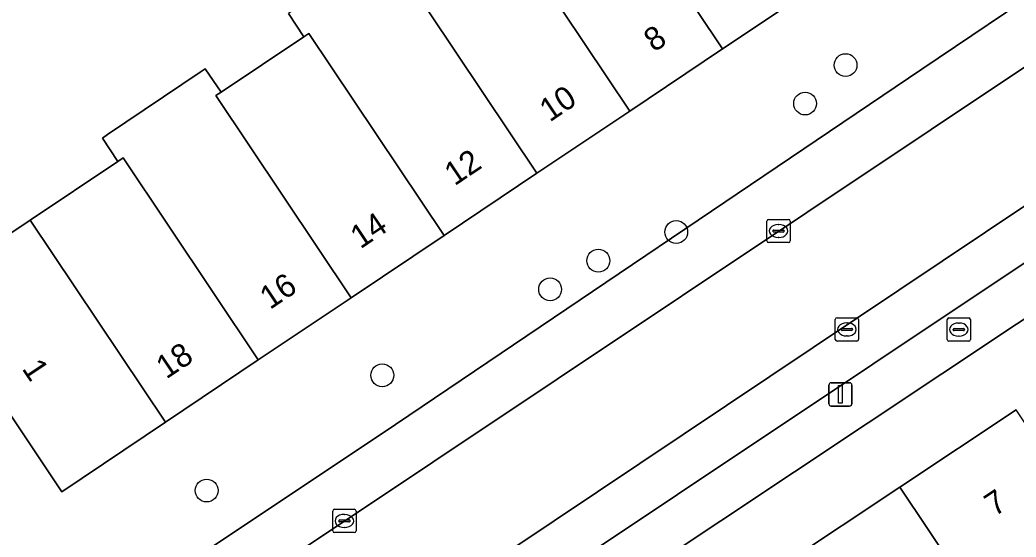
# Model space of a CAD drawing. Extents: x 158352 to 159489, y 383828 to 384603.
# Drawn here: x 158810.26 to 158853.05, y 384458.72 to 384480.93 of the extents above; entities that cross this region are included whole.
import ezdxf

# ---------------------------------------------------------------- set-up
doc = ezdxf.new("R2010")
doc.units = 0
for name, color, linetype in [('IMGEO_Boom', 7, 'Continuous'), ('IMGEO_Brandkraan', 7, 'Continuous'), ('IMGEO_Erf', 7, 'Continuous'), ('IMGEO_Groenvoorziening', 7, 'Continuous'), ('IMGEO_Kolk', 7, 'Continuous'), ('IMGEO_Lichtmast', 7, 'Continuous'), ('IMGEO_Pand', 7, 'Continuous'), ('IMGEO_Pand_nummerreeks', 7, 'Continuous'), ('IMGEO_Parkeervlak_open', 7, 'Continuous'), ('IMGEO_Rijbaan_lokaal_open', 7, 'Continuous'), ('IMGEO_Voetpad_open', 7, 'Continuous')]:
    doc.layers.add(name, color=color, linetype=linetype)

msp = doc.modelspace()

# ---------------------------------------------------------------- linework, layer by layer
at = {"layer": 'IMGEO_Boom'}
for centre in [(158845.724, 384478.986), (158843.983, 384477.337), (158838.451, 384471.819), (158835.105, 384470.589), (158833.035, 384469.358), (158825.826, 384465.668), (158818.282, 384460.72)]:
    msp.add_circle(centre, 0.489, dxfattribs=at)
at = {"layer": 'IMGEO_Brandkraan'}
for p, q in [((158850.087, 384467.205), (158850.087, 384468.057)), ((158850.162, 384468.131), (158851.014, 384468.131)), ((158850.575, 384467.911), (158850.6, 384467.911)), ((158851.088, 384468.057), (158851.088, 384467.205)), ((158850.346, 384467.625), (158850.346, 384467.637)), ((158850.784, 384467.588), (158850.386, 384467.588)), ((158850.389, 384467.674), (158850.787, 384467.674)), ((158850.83, 384467.637), (158850.83, 384467.625)), ((158851.014, 384467.131), (158850.162, 384467.131)), ((158850.598, 384467.351), (158850.573, 384467.351))]:
    msp.add_line(p, q, dxfattribs=at)
for points in [[(158850.087, 384467.205), (158850.087, 384468.057)], [(158850.162, 384468.131), (158851.014, 384468.131)], [(158851.088, 384468.057), (158851.088, 384467.205)], [(158851.014, 384467.131), (158850.162, 384467.131)]]:
    msp.add_lwpolyline(points, dxfattribs=at)
for centre, radius, start, end in [((158850.164, 384468.055), 0.0765, 91.552, 178.448), ((158850.164, 384468.055), 0.0765, 91.552, 178.448), ((158851.012, 384468.055), 0.0765, 1.552, 88.448), ((158851.012, 384468.055), 0.0765, 1.552, 88.448), ((158850.386, 384467.634), 0.0403, 85.8775, 175.7526), ((158850.383, 384467.624), 0.0366, 178.938, 274.7102), ((158850.787, 384467.631), 0.043, 264.8664, 352.4533), ((158850.791, 384467.636), 0.0386, 1.7309, 96.639), ((158850.164, 384467.207), 0.0765, 181.552, 268.448), ((158850.164, 384467.207), 0.0765, 181.552, 268.448), ((158851.012, 384467.207), 0.0765, 271.552, 358.448), ((158851.012, 384467.207), 0.0765, 271.552, 358.448)]:
    msp.add_arc(centre, radius, start, end, dxfattribs=at)
for centre, major_axis, ratio, start_param, end_param in [((158850.574, 384467.631), (-0.387, 0.002), 0.722429, 4.712389, 7.853982), ((158850.599, 384467.631), (-0.39, 0.002), 0.717154, 1.570796, 4.712389)]:
    msp.add_ellipse(centre, major_axis=major_axis, ratio=ratio, start_param=start_param, end_param=end_param, dxfattribs=at)
at = {"layer": 'IMGEO_Erf'}
msp.add_lwpolyline([(158865.767, 384476.314), (158824.454, 384448.838), (158828.581, 384442.633), (158830.834, 384444.121), (158828.404, 384447.801), (158833.585, 384451.247), (158838.609, 384454.589), (158843.054, 384457.545), (158848.053, 384460.87), (158853.047, 384464.192)], dxfattribs=at)
at = {"layer": 'IMGEO_Groenvoorziening'}
for points in [[(158756.032, 384416.448), (158759.672, 384418.896), (158801.455, 384446.936), (158826.388, 384463.558), (158848.997, 384478.808), (158860.431, 384486.52)], [(158844.203, 384482.207), (158840.44, 384479.686), (158836.453, 384477.014), (158832.465, 384474.342), (158828.477, 384471.67), (158824.49, 384468.999), (158820.502, 384466.326), (158816.515, 384463.655), (158812.057, 384460.668), (158806.248, 384469.347), (158810.709, 384472.333), (158814.475, 384474.854), (158813.806, 384475.854), (158814.028, 384476.004), (158818.009, 384478.687), (158818.219, 384478.828), (158818.901, 384477.824), (158822.457, 384480.205), (158821.791, 384481.2)]]:
    msp.add_lwpolyline(points, dxfattribs=at)
at = {"layer": 'IMGEO_Kolk'}
for p, q in [((158842.344, 384471.437), (158842.344, 384472.289)), ((158842.419, 384472.363), (158843.271, 384472.363)), ((158842.832, 384472.143), (158842.857, 384472.143)), ((158843.345, 384472.289), (158843.345, 384471.437)), ((158842.603, 384471.857), (158842.603, 384471.869)), ((158843.041, 384471.82), (158842.643, 384471.82)), ((158842.646, 384471.906), (158843.044, 384471.906)), ((158843.087, 384471.869), (158843.087, 384471.857)), ((158843.271, 384471.363), (158842.419, 384471.363)), ((158842.855, 384471.583), (158842.83, 384471.583)), ((158845.28, 384467.212), (158845.28, 384468.064)), ((158845.355, 384468.138), (158846.207, 384468.138)), ((158845.768, 384467.918), (158845.793, 384467.918)), ((158846.281, 384468.064), (158846.281, 384467.212)), ((158845.539, 384467.632), (158845.539, 384467.644)), ((158845.977, 384467.595), (158845.579, 384467.595)), ((158845.582, 384467.681), (158845.98, 384467.681)), ((158845.791, 384467.358), (158845.766, 384467.358)), ((158846.023, 384467.644), (158846.023, 384467.632)), ((158846.207, 384467.138), (158845.355, 384467.138)), ((158823.697, 384458.988), (158823.697, 384459.84)), ((158823.772, 384459.914), (158824.624, 384459.914)), ((158824.185, 384459.694), (158824.21, 384459.694)), ((158824.698, 384459.84), (158824.698, 384458.988)), ((158823.956, 384459.408), (158823.956, 384459.42)), ((158824.394, 384459.371), (158823.996, 384459.371)), ((158823.999, 384459.457), (158824.397, 384459.457)), ((158824.44, 384459.42), (158824.44, 384459.408)), ((158824.624, 384458.914), (158823.772, 384458.914)), ((158824.208, 384459.134), (158824.183, 384459.134))]:
    msp.add_line(p, q, dxfattribs=at)
for points in [[(158842.344, 384471.437), (158842.344, 384472.289)], [(158842.419, 384472.363), (158843.271, 384472.363)], [(158843.345, 384472.289), (158843.345, 384471.437)], [(158843.271, 384471.363), (158842.419, 384471.363)], [(158845.28, 384467.212), (158845.28, 384468.064)], [(158845.355, 384468.138), (158846.207, 384468.138)], [(158846.281, 384468.064), (158846.281, 384467.212)], [(158846.207, 384467.138), (158845.355, 384467.138)], [(158823.697, 384458.988), (158823.697, 384459.84)], [(158823.772, 384459.914), (158824.624, 384459.914)], [(158824.698, 384459.84), (158824.698, 384458.988)], [(158824.624, 384458.914), (158823.772, 384458.914)]]:
    msp.add_lwpolyline(points, dxfattribs=at)
for centre, radius, start, end in [((158842.421, 384472.287), 0.0765, 91.552, 178.448), ((158842.421, 384472.287), 0.0765, 91.552, 178.448), ((158843.269, 384472.287), 0.0765, 1.552, 88.448), ((158843.269, 384472.287), 0.0765, 1.552, 88.448), ((158842.643, 384471.866), 0.0403, 85.8775, 175.7526), ((158842.64, 384471.856), 0.0366, 178.938, 274.7102), ((158843.044, 384471.863), 0.043, 264.8664, 352.4533), ((158843.048, 384471.868), 0.0386, 1.7309, 96.639), ((158842.421, 384471.439), 0.0765, 181.552, 268.448), ((158842.421, 384471.439), 0.0765, 181.552, 268.448), ((158843.269, 384471.439), 0.0765, 271.552, 358.448), ((158843.269, 384471.439), 0.0765, 271.552, 358.448), ((158845.357, 384468.062), 0.0765, 91.552, 178.448), ((158845.357, 384468.062), 0.0765, 91.552, 178.448), ((158846.205, 384468.062), 0.0765, 1.552, 88.448), ((158846.205, 384468.062), 0.0765, 1.552, 88.448), ((158845.579, 384467.641), 0.0403, 85.8775, 175.7526), ((158845.576, 384467.631), 0.0366, 178.938, 274.7102), ((158845.98, 384467.638), 0.043, 264.8664, 352.4533), ((158845.984, 384467.643), 0.0386, 1.7309, 96.639), ((158845.357, 384467.214), 0.0765, 181.552, 268.448), ((158845.357, 384467.214), 0.0765, 181.552, 268.448), ((158846.205, 384467.214), 0.0765, 271.552, 358.448), ((158846.205, 384467.214), 0.0765, 271.552, 358.448), ((158823.774, 384459.838), 0.0765, 91.552, 178.448), ((158823.774, 384459.838), 0.0765, 91.552, 178.448), ((158824.622, 384459.838), 0.0765, 1.552, 88.448), ((158824.622, 384459.838), 0.0765, 1.552, 88.448), ((158823.996, 384459.417), 0.0403, 85.8775, 175.7526), ((158823.993, 384459.407), 0.0366, 178.938, 274.7102), ((158824.397, 384459.414), 0.043, 264.8664, 352.4533), ((158824.401, 384459.419), 0.0386, 1.7309, 96.639), ((158823.774, 384458.99), 0.0765, 181.552, 268.448), ((158823.774, 384458.99), 0.0765, 181.552, 268.448), ((158824.622, 384458.99), 0.0765, 271.552, 358.448), ((158824.622, 384458.99), 0.0765, 271.552, 358.448)]:
    msp.add_arc(centre, radius, start, end, dxfattribs=at)
for centre, major_axis, ratio, start_param, end_param in [((158842.831, 384471.863), (-0.387, 0.002), 0.722429, 4.712389, 7.853982), ((158842.856, 384471.863), (-0.39, 0.002), 0.717154, 1.570796, 4.712389), ((158845.767, 384467.638), (-0.387, 0.002), 0.722429, 4.712389, 7.853982), ((158845.792, 384467.638), (-0.39, 0.002), 0.717154, 1.570796, 4.712389), ((158824.184, 384459.414), (-0.387, 0.002), 0.722429, 4.712389, 7.853982), ((158824.209, 384459.414), (-0.39, 0.002), 0.717154, 1.570796, 4.712389)]:
    msp.add_ellipse(centre, major_axis=major_axis, ratio=ratio, start_param=start_param, end_param=end_param, dxfattribs=at)
at = {"layer": 'IMGEO_Lichtmast'}
for p, q in [((158845.004, 384464.448), (158845.004, 384465.248)), ((158845.004, 384465.248), (158845.004, 384464.448)), ((158845.104, 384465.348), (158845.894, 384465.348)), ((158845.894, 384465.348), (158845.104, 384465.348)), ((158845.994, 384465.248), (158845.994, 384464.448)), ((158845.994, 384464.448), (158845.994, 384465.248)), ((158845.894, 384464.348), (158845.104, 384464.348)), ((158845.104, 384464.348), (158845.894, 384464.348))]:
    msp.add_line(p, q, dxfattribs=at)
msp.add_lwpolyline([(158845.424, 384465.223), (158845.574, 384465.223), (158845.574, 384464.473), (158845.424, 384464.473), (158845.424, 384465.223)], dxfattribs=at)
for centre, start, end in [((158845.104, 384465.248), 90, 180), ((158845.104, 384465.248), 90, 180), ((158845.894, 384465.248), 0, 90), ((158845.894, 384465.248), 360, 90), ((158845.104, 384464.448), 180, 270), ((158845.104, 384464.448), 180, 270), ((158845.894, 384464.448), 270, 0), ((158845.894, 384464.448), 270, 0)]:
    msp.add_arc(centre, 0.1, start, end, dxfattribs=at)
at = {"layer": 'IMGEO_Pand'}
for points in [[(158839.96, 384489.037), (158840.191, 384489.191), (158838.182, 384492.171), (158837.962, 384492.024), (158833.971, 384489.356), (158840.44, 384479.686), (158844.203, 384482.207), (158844.428, 384482.358)], [(158833.971, 384489.356), (158829.981, 384486.689), (158829.76, 384486.541), (158830.425, 384485.539), (158830.649, 384485.689), (158836.453, 384477.014), (158840.44, 384479.686)], [(158830.649, 384485.689), (158830.425, 384485.539), (158826.891, 384483.17), (158826.662, 384483.017), (158832.465, 384474.342), (158836.453, 384477.014)], [(158826.662, 384483.017), (158826.891, 384483.17), (158826.207, 384484.173), (158825.988, 384484.025), (158822.006, 384481.344), (158821.791, 384481.2), (158822.457, 384480.205), (158822.672, 384480.349), (158828.477, 384471.67), (158832.465, 384474.342)], [(158822.672, 384480.349), (158822.457, 384480.205), (158818.901, 384477.824), (158818.683, 384477.678), (158824.49, 384468.999), (158828.477, 384471.67)], [(158818.683, 384477.678), (158818.901, 384477.824), (158818.219, 384478.828), (158818.009, 384478.687), (158814.028, 384476.004), (158813.806, 384475.854), (158814.475, 384474.854), (158814.698, 384475.003), (158820.502, 384466.326), (158824.49, 384468.999)], [(158814.698, 384475.003), (158814.475, 384474.854), (158810.709, 384472.333), (158816.515, 384463.655), (158820.502, 384466.326)], [(158810.709, 384472.333), (158806.248, 384469.347), (158812.057, 384460.668), (158816.515, 384463.655)], [(158853.047, 384464.192), (158848.053, 384460.87), (158852.977, 384453.51), (158857.962, 384456.845)], [(158847.986, 384450.172), (158852.977, 384453.51), (158848.053, 384460.87), (158843.054, 384457.545)]]:
    msp.add_lwpolyline(points, close=True, dxfattribs=at)
at = {"layer": 'IMGEO_Parkeervlak_open'}
msp.add_lwpolyline([(158820.811, 384450.589), (158821.645, 384449.296), (158863.755, 384477.4), (158862.897, 384478.725), (158862.853, 384479.261), (158820.226, 384450.737)], dxfattribs=at)
at = {"layer": 'IMGEO_Rijbaan_lokaal_open'}
msp.add_lwpolyline([(158817.271, 384454.789), (158820.001, 384450.597), (158820.226, 384450.737), (158862.853, 384479.261), (158860.122, 384483.398)], close=True, dxfattribs=at)
at = {"layer": 'IMGEO_Voetpad_open'}
for points in [[(158744.541, 384406.289), (158761.522, 384417.613), (158799.316, 384442.816), (158817.271, 384454.789), (158860.122, 384483.398), (158863.954, 384485.975), (158863.532, 384488.47), (158860.431, 384486.52), (158848.997, 384478.808), (158826.388, 384463.558), (158801.455, 384446.936), (158759.672, 384418.896), (158756.032, 384416.448), (158743.282, 384407.89)], [(158815.486, 384442.875), (158818.522, 384444.893), (158820.38, 384446.128), (158824.454, 384448.838), (158865.767, 384476.314), (158864.982, 384477.657), (158864.771, 384478.02), (158863.755, 384477.4), (158821.645, 384449.296), (158820.811, 384450.589)]]:
    msp.add_lwpolyline(points, dxfattribs=at)

# ---------------------------------------------------------------- texts
at = {"layer": 'IMGEO_Pand_nummerreeks'}
for s, rotation, p in [('8', 33.8217, (158837.496, 384479.519)), ('10', 33.8217, (158833.017, 384476.518)), ('12', 33.8217, (158828.931, 384473.78)), ('14', 33.8217, (158824.889, 384471.072)), ('16', 33.8217, (158821.003, 384468.468)), ('18', 33.8217, (158816.55, 384465.484)), ('1', 303.7928, (158810.326, 384465.951)), ('7', 33.6064, (158852.123, 384459.584))]:
    msp.add_text(s, height=1, rotation=rotation, dxfattribs=at).set_placement(p)

doc.saveas('drawing.dxf')
